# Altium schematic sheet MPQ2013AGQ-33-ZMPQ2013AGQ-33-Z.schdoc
size 127 x 101 mm
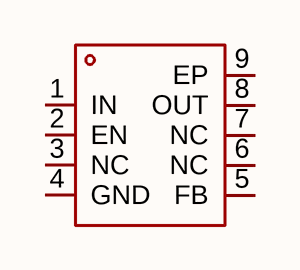
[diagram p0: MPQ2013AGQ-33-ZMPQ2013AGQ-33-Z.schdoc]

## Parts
U?  mpq2013agq-33-z  [QFN-8_L3.0-W3.0-P0.65-TL-EP2.5]  (value not drawn)

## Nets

Not connected (* = marked no-connect by the designer): U? 1(IN) 2(EN) 3(NC) 4(GND) 5(FB) 6(NC) 7(NC) 8(OUT) 9(EP)

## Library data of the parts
U? = mpq2013agq-33-z: 输出极性:正极;工作电压:40V;输出电压:3.3V;输出电流:150mA;电源纹波抑制比(PSRR):58dB@(100Hz);输出类型:固定;; Manufacturer: MPS(芯源); AddInBom: yes; ModelId: 7d7b0c6373f54773b7915f82dc80757a; ModelTransform: 118.18874,118.11,0,0,0,0,0,0,0; Output Configuration: 正极; Voltage - Supply: 40V; Output Voltage: 3.3V; Output Current: 150mA; Voltage Dropout: 700mV@(150mA); standby current: 4.4uA; Output Type: 固定; Number of Outputs: 1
